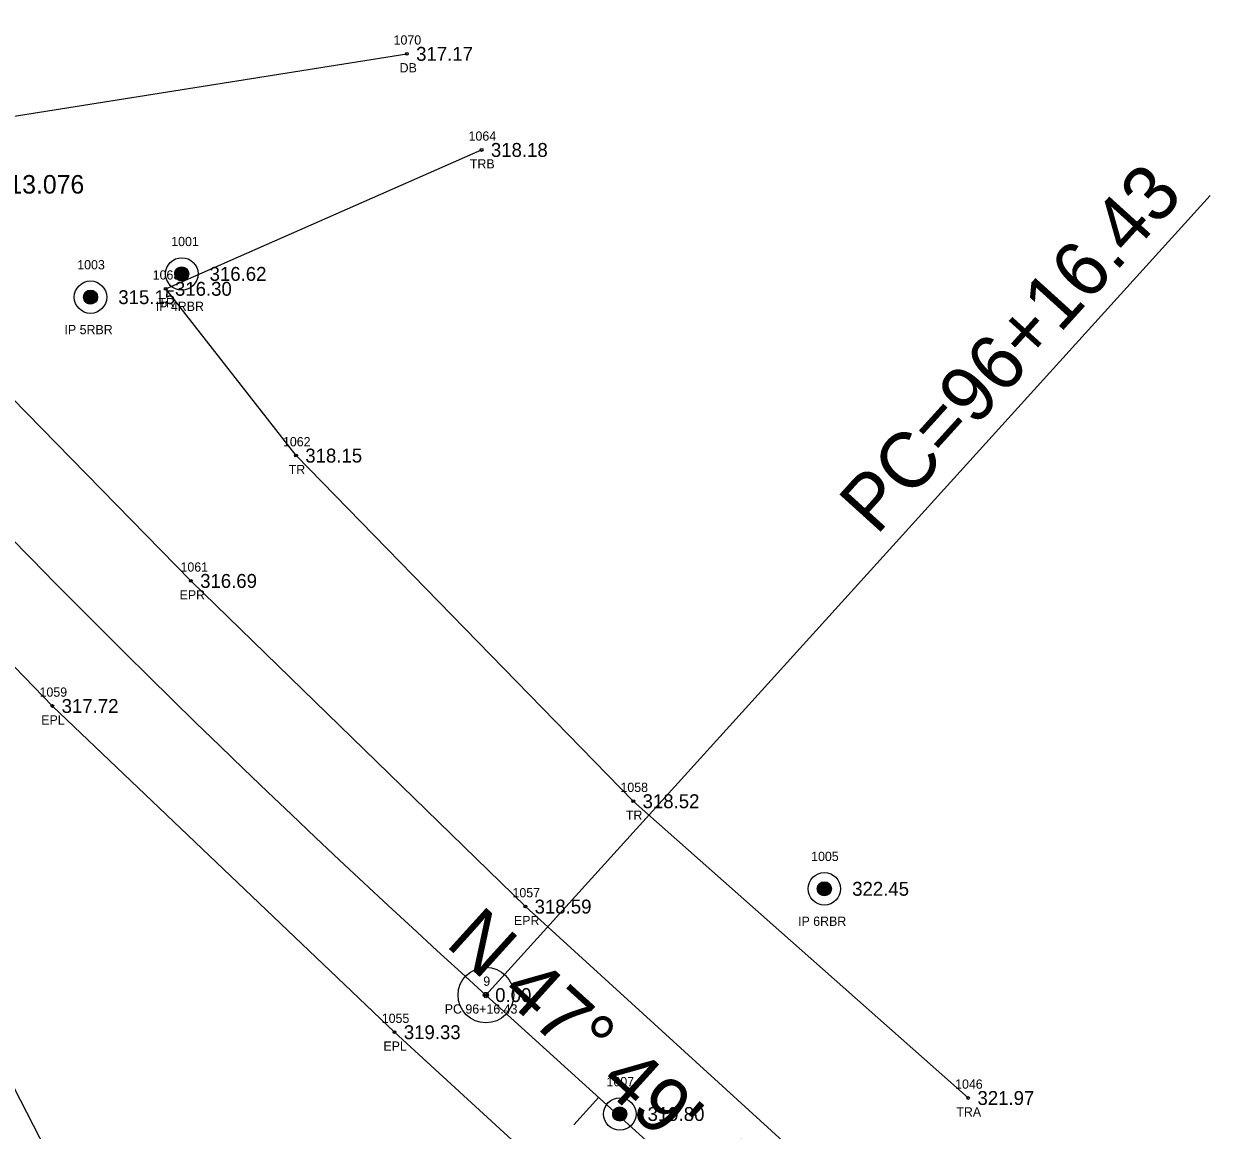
# Model space of a CAD drawing. Extents: x 1865045 to 1867370, y 910391 to 914218.
# Drawn here: x 1866724.3 to 1866852.4, y 910455.2 to 910574.6 of the extents above; entities that cross this region are included whole.
import ezdxf

# ---------------------------------------------------------------- set-up
doc = ezdxf.new("R2010")
doc.units = 0
for name, color, linetype in [('RD_EX_Driveway', 7, 'Continuous'), ('RD_EX_Driveway_txCode', 7, 'Continuous'), ('RD_EX_DV_Prop_txCode', 7, 'Continuous'), ('RD_EX_DV_PropPin', 7, 'Continuous'), ('RD_EX_Road', 7, 'Continuous'), ('RD_EX_Road_txCode', 7, 'Continuous'), ('RD_EX_TX_Driveway_ELEV', 7, 'Continuous'), ('RD_EX_TX_DV_Prop_ELEV', 7, 'Continuous'), ('RD_EX_TX_Road_ELEV', 7, 'Continuous'), ('RD_EX_TX_VEG_ELEV', 7, 'Continuous'), ('RD_EX_VEG', 7, 'Continuous'), ('RD_EX_VEG_txCode', 7, 'Continuous'), ('RD_HC_Cl', 7, 'Continuous'), ('RD_HC_Data', 7, 'Continuous'), ('RD_HC_Data_Tic', 7, 'Continuous'), ('RD_HC_Survey_ELEV', 7, 'Continuous'), ('RD_HC_txCode', 7, 'Continuous'), ('RD_SMD_Locator', 7, 'Continuous'), ('RD_TX_Pipe_ElevEX', 7, 'Continuous')]:
    doc.layers.add(name, color=color, linetype=linetype)

msp = doc.modelspace()

# ---------------------------------------------------------------- linework, layer by layer
at = {"layer": 'RD_EX_Driveway'}
msp.add_line((1866715.42, 910563.39), (1866765.65, 910571.34), dxfattribs=at)
at = {"layer": 'RD_EX_DV_PropPin'}
for p, q in [((1866740.63, 910547.4), (1866740.63, 910547.79)), ((1866740.66, 910547.29), (1866740.66, 910547.89)), ((1866740.7, 910547.22), (1866740.7, 910547.96)), ((1866740.73, 910547.16), (1866740.73, 910548.02)), ((1866740.77, 910547.12), (1866740.77, 910548.07)), ((1866740.8, 910547.08), (1866740.8, 910548.11)), ((1866740.84, 910547.04), (1866740.84, 910548.14)), ((1866740.87, 910547.01), (1866740.87, 910548.17)), ((1866740.91, 910546.98), (1866740.91, 910548.2)), ((1866740.94, 910546.96), (1866740.94, 910548.23)), ((1866740.98, 910546.93), (1866740.98, 910548.25)), ((1866741.01, 910546.92), (1866741.01, 910548.27)), ((1866741.05, 910546.9), (1866741.05, 910548.28)), ((1866741.08, 910546.88), (1866741.08, 910548.3)), ((1866741.12, 910546.87), (1866741.12, 910548.31)), ((1866741.15, 910546.86), (1866741.15, 910548.32)), ((1866741.19, 910546.85), (1866741.19, 910548.33)), ((1866741.22, 910546.84), (1866741.22, 910548.34)), ((1866741.26, 910546.84), (1866741.26, 910548.34)), ((1866741.29, 910546.83), (1866741.29, 910548.35)), ((1866741.33, 910546.83), (1866741.33, 910548.35)), ((1866741.36, 910546.83), (1866741.36, 910548.35)), ((1866741.4, 910546.83), (1866741.4, 910548.35)), ((1866741.43, 910546.83), (1866741.43, 910548.35)), ((1866741.47, 910546.84), (1866741.47, 910548.34)), ((1866741.5, 910546.84), (1866741.5, 910548.34)), ((1866741.54, 910546.85), (1866741.54, 910548.33)), ((1866741.57, 910546.86), (1866741.57, 910548.32)), ((1866741.61, 910546.87), (1866741.61, 910548.31)), ((1866741.64, 910546.88), (1866741.64, 910548.3)), ((1866741.68, 910546.9), (1866741.68, 910548.28)), ((1866741.72, 910546.92), (1866741.72, 910548.27)), ((1866741.75, 910546.93), (1866741.75, 910548.25)), ((1866741.79, 910546.96), (1866741.79, 910548.23)), ((1866741.82, 910546.98), (1866741.82, 910548.2)), ((1866741.86, 910547.01), (1866741.86, 910548.17)), ((1866741.89, 910547.04), (1866741.89, 910548.14)), ((1866741.93, 910547.08), (1866741.93, 910548.11)), ((1866741.96, 910547.12), (1866741.96, 910548.07)), ((1866742, 910547.16), (1866742, 910548.02)), ((1866742.03, 910547.22), (1866742.03, 910547.96)), ((1866742.07, 910547.29), (1866742.07, 910547.89)), ((1866742.1, 910547.4), (1866742.1, 910547.79)), ((1866730.77, 910544.89), (1866730.77, 910545.28)), ((1866730.81, 910544.78), (1866730.81, 910545.38)), ((1866730.84, 910544.71), (1866730.84, 910545.45)), ((1866730.88, 910544.65), (1866730.88, 910545.51)), ((1866730.91, 910544.61), (1866730.91, 910545.56)), ((1866730.95, 910544.57), (1866730.95, 910545.6)), ((1866730.98, 910544.53), (1866730.98, 910545.63)), ((1866731.02, 910544.5), (1866731.02, 910545.66)), ((1866731.05, 910544.47), (1866731.05, 910545.69)), ((1866731.09, 910544.45), (1866731.09, 910545.72)), ((1866731.12, 910544.43), (1866731.12, 910545.74)), ((1866731.16, 910544.41), (1866731.16, 910545.76)), ((1866731.19, 910544.39), (1866731.19, 910545.77)), ((1866731.23, 910544.37), (1866731.23, 910545.79)), ((1866731.26, 910544.36), (1866731.26, 910545.8)), ((1866731.3, 910544.35), (1866731.3, 910545.81)), ((1866731.33, 910544.34), (1866731.33, 910545.82)), ((1866731.37, 910544.33), (1866731.37, 910545.83)), ((1866731.4, 910544.33), (1866731.4, 910545.84)), ((1866731.44, 910544.32), (1866731.44, 910545.84)), ((1866731.47, 910544.32), (1866731.47, 910545.84)), ((1866731.51, 910544.32), (1866731.51, 910545.84)), ((1866731.54, 910544.32), (1866731.54, 910545.84)), ((1866731.58, 910544.32), (1866731.58, 910545.84)), ((1866731.61, 910544.33), (1866731.61, 910545.84)), ((1866731.65, 910544.33), (1866731.65, 910545.83)), ((1866731.68, 910544.34), (1866731.68, 910545.82)), ((1866731.72, 910544.35), (1866731.72, 910545.81)), ((1866731.75, 910544.36), (1866731.75, 910545.8)), ((1866731.79, 910544.37), (1866731.79, 910545.79)), ((1866731.82, 910544.39), (1866731.82, 910545.77)), ((1866731.86, 910544.41), (1866731.86, 910545.76)), ((1866731.89, 910544.43), (1866731.89, 910545.74)), ((1866731.93, 910544.45), (1866731.93, 910545.72)), ((1866731.96, 910544.47), (1866731.96, 910545.69)), ((1866732, 910544.5), (1866732, 910545.66)), ((1866732.03, 910544.53), (1866732.03, 910545.63)), ((1866732.07, 910544.57), (1866732.07, 910545.6)), ((1866732.1, 910544.61), (1866732.1, 910545.56)), ((1866732.14, 910544.65), (1866732.14, 910545.51)), ((1866732.17, 910544.71), (1866732.17, 910545.45)), ((1866732.21, 910544.78), (1866732.21, 910545.38)), ((1866732.24, 910544.89), (1866732.24, 910545.28)), ((1866809.97, 910481.02), (1866809.97, 910481.42)), ((1866810.01, 910480.92), (1866810.01, 910481.52)), ((1866810.04, 910480.85), (1866810.04, 910481.59)), ((1866810.08, 910480.79), (1866810.08, 910481.65)), ((1866810.11, 910480.74), (1866810.11, 910481.69)), ((1866810.15, 910480.7), (1866810.15, 910481.73)), ((1866810.18, 910480.67), (1866810.18, 910481.77)), ((1866810.22, 910480.64), (1866810.22, 910481.8)), ((1866810.25, 910480.61), (1866810.25, 910481.83)), ((1866810.29, 910480.58), (1866810.29, 910481.85)), ((1866810.32, 910480.56), (1866810.32, 910481.88)), ((1866810.36, 910480.54), (1866810.36, 910481.89)), ((1866810.39, 910480.53), (1866810.39, 910481.91)), ((1866810.43, 910480.51), (1866810.43, 910481.93)), ((1866810.46, 910480.5), (1866810.46, 910481.94)), ((1866810.5, 910480.49), (1866810.5, 910481.95)), ((1866810.53, 910480.48), (1866810.53, 910481.96)), ((1866810.57, 910480.47), (1866810.57, 910481.97)), ((1866810.6, 910480.47), (1866810.6, 910481.97)), ((1866810.64, 910480.46), (1866810.64, 910481.98)), ((1866810.67, 910480.46), (1866810.67, 910481.98)), ((1866810.71, 910480.46), (1866810.71, 910481.98)), ((1866810.74, 910480.46), (1866810.74, 910481.98)), ((1866810.78, 910480.46), (1866810.78, 910481.98)), ((1866810.81, 910480.47), (1866810.81, 910481.97)), ((1866810.85, 910480.47), (1866810.85, 910481.97)), ((1866810.88, 910480.48), (1866810.88, 910481.96)), ((1866810.92, 910480.49), (1866810.92, 910481.95)), ((1866810.95, 910480.5), (1866810.95, 910481.94)), ((1866810.99, 910480.51), (1866810.99, 910481.93)), ((1866811.02, 910480.53), (1866811.02, 910481.91)), ((1866811.06, 910480.54), (1866811.06, 910481.89)), ((1866811.09, 910480.56), (1866811.09, 910481.88)), ((1866811.13, 910480.58), (1866811.13, 910481.85)), ((1866811.16, 910480.61), (1866811.16, 910481.83)), ((1866811.2, 910480.64), (1866811.2, 910481.8)), ((1866811.23, 910480.67), (1866811.23, 910481.77)), ((1866811.27, 910480.7), (1866811.27, 910481.73)), ((1866811.3, 910480.74), (1866811.3, 910481.69)), ((1866811.34, 910480.79), (1866811.34, 910481.65)), ((1866811.37, 910480.85), (1866811.37, 910481.59)), ((1866811.41, 910480.92), (1866811.41, 910481.52)), ((1866811.44, 910481.02), (1866811.44, 910481.42)), ((1866787.89, 910456.72), (1866787.89, 910457.11)), ((1866787.93, 910456.62), (1866787.93, 910457.21)), ((1866787.96, 910456.54), (1866787.96, 910457.28)), ((1866788, 910456.49), (1866788, 910457.34)), ((1866788.03, 910456.44), (1866788.03, 910457.39)), ((1866788.07, 910456.4), (1866788.07, 910457.43)), ((1866788.1, 910456.36), (1866788.1, 910457.46)), ((1866788.14, 910456.33), (1866788.14, 910457.5)), ((1866788.17, 910456.3), (1866788.17, 910457.52)), ((1866788.21, 910456.28), (1866788.21, 910457.55)), ((1866788.24, 910456.26), (1866788.24, 910457.57)), ((1866788.28, 910456.24), (1866788.28, 910457.59)), ((1866788.31, 910456.22), (1866788.31, 910457.61)), ((1866788.35, 910456.21), (1866788.35, 910457.62)), ((1866788.38, 910456.19), (1866788.38, 910457.63)), ((1866788.42, 910456.18), (1866788.42, 910457.64)), ((1866788.45, 910456.17), (1866788.45, 910457.65)), ((1866788.49, 910456.17), (1866788.49, 910457.66)), ((1866788.52, 910456.16), (1866788.52, 910457.67)), ((1866788.56, 910456.16), (1866788.56, 910457.67)), ((1866788.59, 910456.15), (1866788.59, 910457.67)), ((1866788.63, 910456.15), (1866788.63, 910457.67)), ((1866788.66, 910456.15), (1866788.66, 910457.67)), ((1866788.7, 910456.16), (1866788.7, 910457.67)), ((1866788.73, 910456.16), (1866788.73, 910457.67)), ((1866788.77, 910456.17), (1866788.77, 910457.66)), ((1866788.8, 910456.17), (1866788.8, 910457.65)), ((1866788.84, 910456.18), (1866788.84, 910457.64)), ((1866788.87, 910456.19), (1866788.87, 910457.63)), ((1866788.91, 910456.21), (1866788.91, 910457.62)), ((1866788.94, 910456.22), (1866788.94, 910457.61)), ((1866788.98, 910456.24), (1866788.98, 910457.59)), ((1866789.01, 910456.26), (1866789.01, 910457.57)), ((1866789.05, 910456.28), (1866789.05, 910457.55)), ((1866789.08, 910456.3), (1866789.08, 910457.52)), ((1866789.12, 910456.33), (1866789.12, 910457.5)), ((1866789.15, 910456.36), (1866789.15, 910457.46)), ((1866789.19, 910456.4), (1866789.19, 910457.43)), ((1866789.22, 910456.44), (1866789.22, 910457.39)), ((1866789.26, 910456.49), (1866789.26, 910457.34)), ((1866789.29, 910456.54), (1866789.29, 910457.28)), ((1866789.33, 910456.62), (1866789.33, 910457.21)), ((1866789.36, 910456.72), (1866789.36, 910457.11))]:
    msp.add_line(p, q, dxfattribs=at)
for centre, radius in [((1866741.36, 910547.59), 1.75), ((1866741.36, 910547.59), 0.761), ((1866731.51, 910545.08), 1.75), ((1866731.51, 910545.08), 0.761), ((1866810.71, 910481.22), 1.75), ((1866810.71, 910481.22), 0.761), ((1866788.63, 910456.91), 1.75), ((1866788.63, 910456.91), 0.761)]:
    msp.add_circle(centre, radius, dxfattribs=at)
at = {"layer": 'RD_EX_Road'}
for points in [[(1866813.99, 910446.88), (1866778.44, 910479.3), (1866742.34, 910514.45), (1866706.87, 910550.71), (1866695.16, 910564.33), (1866672.6, 910589.75), (1866641.04, 910629.03), (1866609.7, 910670.28), (1866582.23, 910711.25), (1866556.44, 910754.58), (1866532.04, 910798.87), (1866507.56, 910846.03), (1866483.5, 910895.43), (1866461.16, 910941.96), (1866414.86, 911037.95), (1866406.11, 911034.1)], [(1866800.58, 910432.45), (1866764.32, 910465.74), (1866727.39, 910500.95), (1866691.9, 910537.68), (1866657.44, 910577.07), (1866624.97, 910617.36), (1866593.69, 910658.89), (1866565.16, 910701.48), (1866538.98, 910745.57), (1866531.34, 910758.5), (1866513.94, 910791.05), (1866489.48, 910838.44), (1866465.73, 910886.02), (1866443.47, 910933.62), (1866397.5, 911029.82), (1866406.11, 911034.1)]]:
    msp.add_lwpolyline(points, dxfattribs=at)
at = {"layer": 'RD_EX_VEG'}
for points in [[(1866770.74, 910392.93), (1866734.38, 910438.07), (1866709.99, 910485.53), (1866679.02, 910526.15), (1866645.41, 910567.43), (1866612.91, 910609.64), (1866580.57, 910649.92), (1866452.86, 910898.44)], [(1866826.23, 910458.64), (1866790.09, 910490.67), (1866753.69, 910527.98), (1866739.62, 910545.98), (1866773.72, 910560.97)]]:
    msp.add_lwpolyline(points, dxfattribs=at)
at = {"layer": 'RD_HC_Cl'}
msp.add_line((1866807.33, 910439.72), (1866774.18, 910469.75), dxfattribs=at)
msp.add_arc((1867567.42, 911345.48), 1181.58, 205.67399, 227.8297, dxfattribs=at)
at = {"layer": 'RD_HC_Data'}
msp.add_line((1866774.18, 910469.75), (1866852.36, 910556.05), dxfattribs=at)
for radius in [3, 0.282]:
    msp.add_circle((1866774.18, 910469.75), radius, dxfattribs=at)
at = {"layer": 'RD_HC_Data_Tic'}
msp.add_line((1866786.36, 910458.72), (1866783.67, 910455.75), dxfattribs=at)
at = {"layer": 'RD_SMD_Locator'}
for centre in [(1866765.65, 910571.34), (1866773.72, 910560.97), (1866741.36, 910547.59), (1866731.51, 910545.08), (1866739.62, 910545.98), (1866753.69, 910527.98), (1866742.34, 910514.45), (1866727.39, 910500.95), (1866790.09, 910490.67), (1866810.71, 910481.22), (1866778.44, 910479.3), (1866774.18, 910469.75), (1866764.32, 910465.74), (1866826.23, 910458.64), (1866788.63, 910456.91)]:
    msp.add_circle(centre, 0.15, dxfattribs=at)

# ---------------------------------------------------------------- texts
at = {"layer": 'RD_EX_Driveway_txCode'}
for s, p in [('1070', (1866764.22, 910572.34)), ('DB', (1866764.87, 910569.34))]:
    msp.add_text(s, height=1, dxfattribs=at).set_placement(p)
at = {"layer": 'RD_EX_DV_Prop_txCode'}
for s, p in [('1001', (1866740.22, 910550.59)), ('1003', (1866730.08, 910548.08)), ('IP 4RBR', (1866738.55, 910543.59)), ('IP 5RBR', (1866728.7, 910541.08)), ('1005', (1866809.28, 910484.22)), ('IP 6RBR', (1866807.87, 910477.22)), ('1007', (1866787.2, 910459.91))]:
    msp.add_text(s, height=1, dxfattribs=at).set_placement(p)
at = {"layer": 'RD_EX_Road_txCode'}
for s, p in [('1061', (1866741.22, 910515.45)), ('EPR', (1866741.12, 910512.45)), ('1059', (1866726.01, 910501.95)), ('EPL', (1866726.19, 910498.95)), ('1057', (1866777.05, 910480.3)), ('EPR', (1866777.21, 910477.3)), ('1055', (1866762.94, 910466.74)), ('EPL', (1866763.12, 910463.74))]:
    msp.add_text(s, height=1, dxfattribs=at).set_placement(p)
at = {"layer": 'RD_EX_TX_Driveway_ELEV'}
msp.add_text('317.17', height=1.5, dxfattribs=at).set_placement((1866766.65, 910570.59))
at = {"layer": 'RD_EX_TX_DV_Prop_ELEV'}
for s, p in [('316.62', (1866744.36, 910546.84)), ('315.15', (1866734.51, 910544.33)), ('322.45', (1866813.71, 910480.47)), ('319.80', (1866791.63, 910456.16))]:
    msp.add_text(s, height=1.5, dxfattribs=at).set_placement(p)
at = {"layer": 'RD_EX_TX_Road_ELEV'}
for s, p in [('316.69', (1866743.34, 910513.7)), ('317.72', (1866728.39, 910500.2)), ('318.59', (1866779.44, 910478.55)), ('319.33', (1866765.32, 910464.99))]:
    msp.add_text(s, height=1.5, dxfattribs=at).set_placement(p)
at = {"layer": 'RD_EX_TX_VEG_ELEV'}
for s, p in [('318.18', (1866774.72, 910560.22)), ('316.30', (1866740.62, 910545.23)), ('318.15', (1866754.69, 910527.23)), ('318.52', (1866791.09, 910489.92)), ('321.97', (1866827.23, 910457.89))]:
    msp.add_text(s, height=1.5, dxfattribs=at).set_placement(p)
at = {"layer": 'RD_EX_VEG_txCode'}
for s, p in [('1064', (1866772.31, 910561.97)), ('TRB', (1866772.45, 910558.97)), ('1063', (1866738.22, 910546.98)), ('TR', (1866738.83, 910543.98)), ('1062', (1866752.28, 910528.98)), ('TR', (1866752.9, 910525.98)), ('1058', (1866788.7, 910491.67)), ('TR', (1866789.29, 910488.67)), ('1046', (1866824.82, 910459.64)), ('TRA', (1866824.95, 910456.64))]:
    msp.add_text(s, height=1, dxfattribs=at).set_placement(p)
at = {"layer": 'RD_HC_Data'}
for s, rotation, p in [('PC=96+16.43', 47.8297, (1866816.34, 910519.27)), ('N 47%%d 49\' 47" W', 317.8297, (1866769.7, 910475.16))]:
    msp.add_text(s, height=6, rotation=rotation, dxfattribs=at).set_placement(p)
at = {"layer": 'RD_HC_Survey_ELEV'}
msp.add_text('0.00', height=1.5, dxfattribs=at).set_placement((1866775.18, 910469))
at = {"layer": 'RD_HC_txCode'}
for s, p in [('9', (1866773.9, 910470.75)), ('PC 96+16.43', (1866769.74, 910467.75))]:
    msp.add_text(s, height=1, dxfattribs=at).set_placement(p)
at = {"layer": 'RD_TX_Pipe_ElevEX'}
msp.add_text('EL=313.076', height=2, dxfattribs=at).set_placement((1866716.33, 910556.26))

doc.saveas('drawing.dxf')
